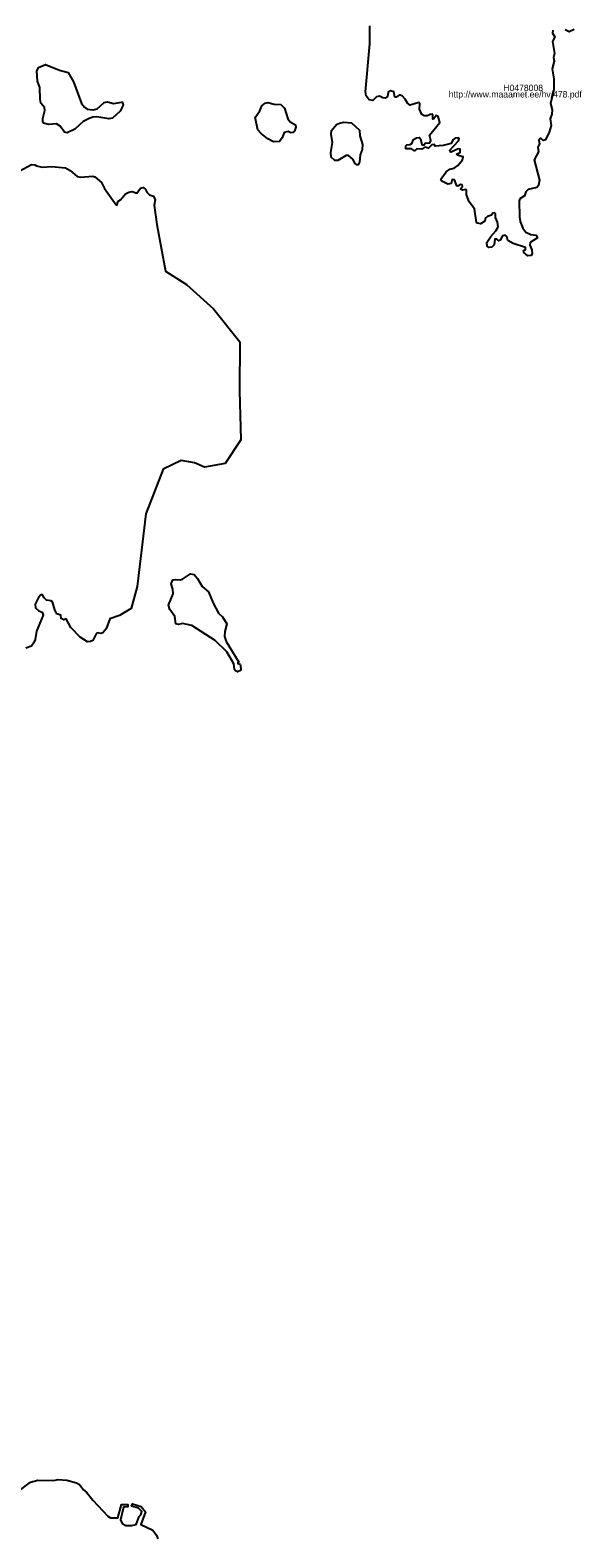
# Model space of a CAD drawing. Extents: x 369010 to 739155, y 6377141 to 6634081.
# Drawn here: x 456915 to 459057, y 6483613 to 6489475 of the extents above; entities that cross this region are included whole.
import ezdxf

# ---------------------------------------------------------------- set-up
doc = ezdxf.new("R2010")
doc.units = 0
for name, color, linetype in [('H_LINK', 7, 'Continuous'), ('H_PIIR', 7, 'Continuous'), ('H_TUNNUS', 7, 'Continuous')]:
    doc.layers.add(name, color=color, linetype=linetype)

msp = doc.modelspace()

# ---------------------------------------------------------------- linework, layer by layer
at = {"layer": 'H_PIIR'}
for points in [[(458944.18, 6489475.62), (458942.9, 6489464.13), (458951.52, 6489449.4399), (458943, 6489431.33), (458950.7199, 6489383.97), (458946.7701, 6489369.62), (458948.9699, 6489354.2799), (458941.75, 6489324.4101), (458948.33, 6489286.58), (458948.33, 6489244.43), (458935.2401, 6489190.78), (458940.9801, 6489165.24), (458939.7099, 6489148.63), (458933.9599, 6489130.75), (458937.15, 6489104.5701), (458929.4901, 6489078.38), (458915.76, 6489048.68), (458906.5, 6489045.81), (458898.51, 6489053.48), (458894.3601, 6489053.7901), (458889.91, 6489047.04), (458892.4199, 6489033.4099), (458886.0599, 6489020.58), (458888.62, 6489002.06), (458872.01, 6488971.7299), (458892.13, 6488891.9), (458888.62, 6488870.8201), (458881.91, 6488863.48), (458848.38, 6488855.1699), (458839.12, 6488847.1901), (458833.6901, 6488830.8999), (458816.4501, 6488819.73), (458812.9401, 6488811.4301), (458814.21, 6488749.48), (458817.09, 6488731.6), (458827.2999, 6488704.77), (458838.7999, 6488690.4), (458858.6, 6488680.5001), (458879.04, 6488678.5899), (458884.14, 6488668.05), (458856.6799, 6488649.8501), (458855.0901, 6488639.3099), (458862.4299, 6488621.75), (458864.03, 6488605.14), (458859.5599, 6488599.0801), (458847.4199, 6488598.4399), (458832.09, 6488610.89), (458830.5, 6488618.23), (458837.52, 6488622.0699), (458837.52, 6488630.05), (458790.26, 6488645.6999), (458768.87, 6488657.1899), (458765.36, 6488672.8399), (458758.5999, 6488678.1801), (458748.7499, 6488675.7099), (458740.1299, 6488659.1101), (458732.7801, 6488656.2301), (458726.72, 6488662.94), (458719.5001, 6488663.1101), (458716.6301, 6488640.15), (458707.8801, 6488631.65), (458695.42, 6488630.6899), (458688.7199, 6488634.8401), (458688.08, 6488650.17), (458703.7299, 6488673.4801), (458723.2, 6488694.55), (458731.83, 6488710.52), (458729.2701, 6488728.4), (458721.6099, 6488746.2801), (458720.97, 6488760.0099), (458717.1401, 6488764.48), (458711.3901, 6488764.1701), (458705.6401, 6488755.8599), (458690.0001, 6488751.07), (458683.29, 6488745.33), (458680.42, 6488732.2299), (458663.4901, 6488722.33), (458651.68, 6488724.2501), (458647.1999, 6488728.08), (458640.18, 6488780.7699), (458619.74, 6488807.59), (458608.5699, 6488834.4199), (458608.5699, 6488852.2999), (458606.01, 6488855.8101), (458592.92, 6488852.62), (458586.2101, 6488857.4099), (458592.92, 6488869.22), (458592.6001, 6488874.3301), (458586.53, 6488875.61), (458575.04, 6488869.22), (458570.89, 6488870.5), (458562.26, 6488893.17), (458553.3201, 6488894.13), (458549.49, 6488879.12), (458536.08, 6488876.89), (458513.09, 6488888.38), (458508.9401, 6488896.37), (458530.33, 6488924.79), (458544.38, 6488934.3701), (458561.3099, 6488938.1999), (458575.6799, 6488949.3701), (458593.5599, 6488971.41), (458595.79, 6488983.2199), (458573.12, 6488989.29), (458571.84, 6488995.04), (458583.9201, 6489000.0501), (458584.3599, 6489012.7701), (458576.68, 6489013.65), (458549.49, 6489000.79), (458545.34, 6489002.7), (458544.0601, 6489009.09), (458577.5901, 6489045.49), (458580.78, 6489054.43), (458577.5901, 6489056.35), (458564.8201, 6489055.3899), (458555.24, 6489048.68), (458548.85, 6489034.95), (458518.84, 6489026.6501), (458487.76, 6489023.7201), (458483.4501, 6489030.9), (458473.76, 6489029.4599), (458461.0401, 6489017.07), (458446.67, 6489020.9001), (458435.81, 6489012.6), (458416.0001, 6489013.3201), (458407.3901, 6489006.14), (458395.55, 6489013.3201), (458373.2199, 6489013.2399), (458372.9, 6489025.06), (458376.7201, 6489029.4599), (458389.9901, 6489030.18), (458397.17, 6489034.6299), (458402.91, 6489049.5599), (458414.42, 6489056.6701), (458425.91, 6489058.2599), (458430.54, 6489052.79), (458435.5601, 6489030.9), (458443.0901, 6489027.6699), (458448.47, 6489036.2799), (458466.1501, 6489037.83), (458469.98, 6489046.45), (458465.83, 6489067.5199), (458505.74, 6489116.38), (458499.0401, 6489140.01), (458491.06, 6489143.84), (458482.11, 6489130.4299), (458477.6399, 6489129.1599), (458478.2801, 6489144.48), (458475.4101, 6489148.3099), (458467.67, 6489147.87), (458457.63, 6489142.13), (458444.7499, 6489142.25), (458435.17, 6489147.36), (458426.2299, 6489168.4299), (458427.5101, 6489188.55), (458423.68, 6489194.3), (458390.4699, 6489183.12), (458379.93, 6489191.1001), (458371.31, 6489207.39), (458360.77, 6489218.2501), (458348.64, 6489223.9901), (458335.54, 6489215.05), (458330.4299, 6489215.3701), (458326.28, 6489235.17), (458313.1899, 6489239.0001), (458304.5701, 6489233.89), (458302.65, 6489216.9699), (458292.75, 6489211.2201), (458283.8101, 6489211.54), (458271.0399, 6489218.56), (458259.95, 6489216.04), (458245.2501, 6489201.3299), (458230.49, 6489203.88), (458219.63, 6489220.16), (458217.07, 6489235.4901), (458234, 6489422.62), (458234, 6489491.5899)], [(459027.5199, 6489477.54), (459008.04, 6489469.2401), (458992.08, 6489475.9399)], [(456871.4401, 6488927.02), (456919.3401, 6488953.2099), (456932.4299, 6488952.2501), (456938.8199, 6488947.4599), (456961.81, 6488942.03), (456998.8499, 6488944.5799), (457051.22, 6488939.4801), (457070.3799, 6488930.2199), (457096.8799, 6488906.26), (457110.61, 6488904.03), (457158.51, 6488908.1799), (457166.1799, 6488905.3099), (457191.72, 6488883.27), (457202.9, 6488859.64), (457248.56, 6488796.4201), (457252.7099, 6488796.1), (457255.27, 6488808.87), (457265.4801, 6488816.22), (457284.64, 6488838.5701), (457297.42, 6488845.27), (457311.15, 6488847.51), (457329.03, 6488842.08), (457342.44, 6488861.5599), (457353.3, 6488863.16), (457361.2801, 6488857.73), (457367.6701, 6488845.28), (457378.1, 6488835.6601), (457393.17, 6488829.56), (457399.6, 6488815.26), (457396.4101, 6488795.46), (457406.2688, 6488720.1995), (457439.6064, 6488537.6366), (457522.1566, 6488486.8365), (457626.9318, 6488391.5863), (457728.532, 6488262.9985), (457726.9445, 6488072.4982), (457733.2945, 6487881.9978), (457671.3819, 6487789.9226), (457592.0067, 6487775.6351), (457552.3191, 6487793.0976), (457501.519, 6487802.6226), (457431.6689, 6487767.6976), (457363.4063, 6487594.6597), (457330.0687, 6487312.0841), (457306.2561, 6487226.359), (457261.8061, 6487199.3714), (457223.9701, 6487186.0601), (457209.28, 6487147.74), (457196.1901, 6487132.4101), (457189.1699, 6487129.22), (457175.12, 6487131.46), (457170.65, 6487128.2599), (457157.87, 6487102.72), (457148.2899, 6487097.93), (457137.4401, 6487096.97), (457108.7, 6487115.49), (457072.6099, 6487153.1701), (457054.7299, 6487185.74), (457044.9999, 6487182.23), (457035.3101, 6487187.2601), (457033.16, 6487200.8899), (457018.4499, 6487206.2701), (457010.02, 6487221.8201), (457000.76, 6487252.16), (456995.3399, 6487256.63), (456977.77, 6487259.1899), (456969.4701, 6487268.4499), (456962.13, 6487279.3), (456956.0599, 6487279.3), (456946.8, 6487269.7201), (456934.03, 6487242.9), (456934.98, 6487228.85), (456947.76, 6487217.6699), (456961.17, 6487212.24), (456965.3199, 6487200.11), (456939.77, 6487138.1601), (456934.03, 6487105.59), (456927.9601, 6487091.54), (456920.2999, 6487080.68), (456897.62, 6487072.7)], [(456867.57, 6483793.6547), (456916.52, 6483828.8746), (456944.39, 6483837.3947), (457006.51, 6483836.2347), (457022.38, 6483840.1046), (457057.2101, 6483837.7846), (457094.37, 6483826.5646), (457106.55, 6483819.9747), (457121.6499, 6483799.8547), (457133.2599, 6483790.1747), (457157.6401, 6483759.9847), (457216.2699, 6483697.6647), (457227.11, 6483690.3047), (457254.9799, 6483690.6946), (457268.9101, 6483742.9546), (457293.6799, 6483742.5646), (457293.29, 6483733.6646), (457277.0401, 6483732.8847), (457265.4301, 6483682.9546), (457272.3901, 6483669.4047), (457286.33, 6483660.5046), (457309.9401, 6483660.8847), (457326.19, 6483665.1446), (457338.38, 6483695.7246), (457344.9599, 6483701.9147), (457347.67, 6483715.8546), (457334.9, 6483727.8547), (457308.5799, 6483735.9846), (457312.0599, 6483744.8846), (457345.7401, 6483734.8246), (457361.99, 6483713.9147), (457344.5801, 6483664.7547), (457391.02, 6483642.3047), (457405.7301, 6483622.9546), (457410.96, 6483609.0247)]]:
    msp.add_lwpolyline(points, dxfattribs=at)
for points in [[(457135.84, 6489167.79), (457159.1499, 6489165.24), (457174.48, 6489170.03), (457201.62, 6489193.9801), (457215.35, 6489197.17), (457238.3401, 6489190.4601), (457269.0001, 6489195.89), (457273.15, 6489194.9399), (457275.38, 6489183.12), (457264.53, 6489160.13), (457234.1899, 6489133.3099), (457219.8199, 6489130.11), (457173.84, 6489138.4199), (457158.51, 6489137.4601), (457143.1801, 6489132.35), (457120.19, 6489120.21), (457088.58, 6489090.5199), (457058.2399, 6489075.5099), (457048.0201, 6489079.0199), (457031.42, 6489102.33), (457016.7299, 6489110.63), (456986.0799, 6489109.0399), (456966.92, 6489113.51), (456964.04, 6489117.02), (456963.4, 6489132.03), (456971.39, 6489162.6799), (456970.75, 6489174.5), (456956.6999, 6489191.42), (456953.1799, 6489206.75), (456952.55, 6489252.7299), (456942.65, 6489277.0001), (456940.41, 6489315.32), (456947.4399, 6489330.6501), (456974.5799, 6489342.1399), (457028.8599, 6489320.11), (457062.3901, 6489310.5301), (457082.83, 6489274.45), (457113.49, 6489190.15), (457125.3001, 6489175.4601)], [(457941.5, 6489083.1701), (457935.11, 6489077.4201), (457926.81, 6489075.83), (457916.59, 6489081.26), (457901.2601, 6489077.74), (457893.2801, 6489056.0301), (457882.7399, 6489042.94), (457859.7501, 6489041.0201), (457837.08, 6489052.5199), (457811.2099, 6489073.2699), (457798.4399, 6489088.2799), (457788.54, 6489135.22), (457806.42, 6489162.04), (457814.7201, 6489181.52), (457826.8601, 6489191.74), (457838.04, 6489193.66), (457861.66, 6489186.9499), (457887.85, 6489185.99), (457902.86, 6489172.5801), (457915.31, 6489130.75), (457923.93, 6489119.26), (457945.33, 6489107.12), (457945.97, 6489097.5399)], [(458196.32, 6488990.2501), (458194.08, 6488962.15), (458188.6501, 6488952.2501), (458182.9101, 6488951.6101), (458176.2, 6488956.4), (458167.58, 6488974.28), (458151.29, 6488988.0101), (458141.3901, 6488988.0101), (458108.82, 6488968.8499), (458097.3299, 6488968.8499), (458083.92, 6488980.9899), (458081.68, 6488999.83), (458089.02, 6489038.1501), (458082.9599, 6489070.72), (458085.19, 6489084.7699), (458104.3499, 6489108.08), (458116.17, 6489114.15), (458133.0899, 6489117.6599), (458162.1501, 6489114.7799), (458193.44, 6489086.0501), (458195.0401, 6489064.97), (458204.62, 6489031.1199), (458203.6601, 6489011.32)], [(457565.01, 6487343.17), (457582.2601, 6487312.51), (457607.16, 6487291.44), (457625.04, 6487246.73), (457645.8, 6487209.0499), (457662.09, 6487194.6801), (457678.0501, 6487166.58), (457670.07, 6487136.8799), (457669.75, 6487117.72), (457676.1399, 6487098.57), (457724.99, 6487018.0999), (457720.84, 6487017.14), (457720.84, 6487012.9901), (457729.7799, 6487009.4701), (457732.02, 6487004.05), (457733.2999, 6486989.68), (457730.74, 6486985.1999), (457720.2001, 6486980.1001), (457711.8999, 6486983.93), (457708.71, 6486989.68), (457705.83, 6487011.0699), (457678.0501, 6487058.65), (457633.0301, 6487102.08), (457542.9801, 6487160.2), (457506.5799, 6487168.5), (457490.29, 6487163.71), (457480.39, 6487167.5399), (457476.88, 6487195.96), (457456.53, 6487222.3399), (457451.97, 6487239.0699), (457470.1699, 6487283.77), (457468.9, 6487301.66), (457461.5499, 6487322.0899), (457468.5801, 6487337.7399), (457479.11, 6487339.66), (457497, 6487337.42), (457505.9399, 6487340.3), (457536.91, 6487361.05), (457551.76, 6487358.66)]]:
    msp.add_lwpolyline(points, close=True, dxfattribs=at)

# ---------------------------------------------------------------- texts
at = {"layer": 'H_LINK'}
msp.add_text('http://www.maaamet.ee/hv/478.pdf', height=25, dxfattribs=at).set_placement((458540.0159, 6489213.4828))
at = {"layer": 'H_TUNNUS'}
msp.add_text('H0478008', height=25, dxfattribs=at).set_placement((458751.8705, 6489238.4828))

doc.saveas('drawing.dxf')
